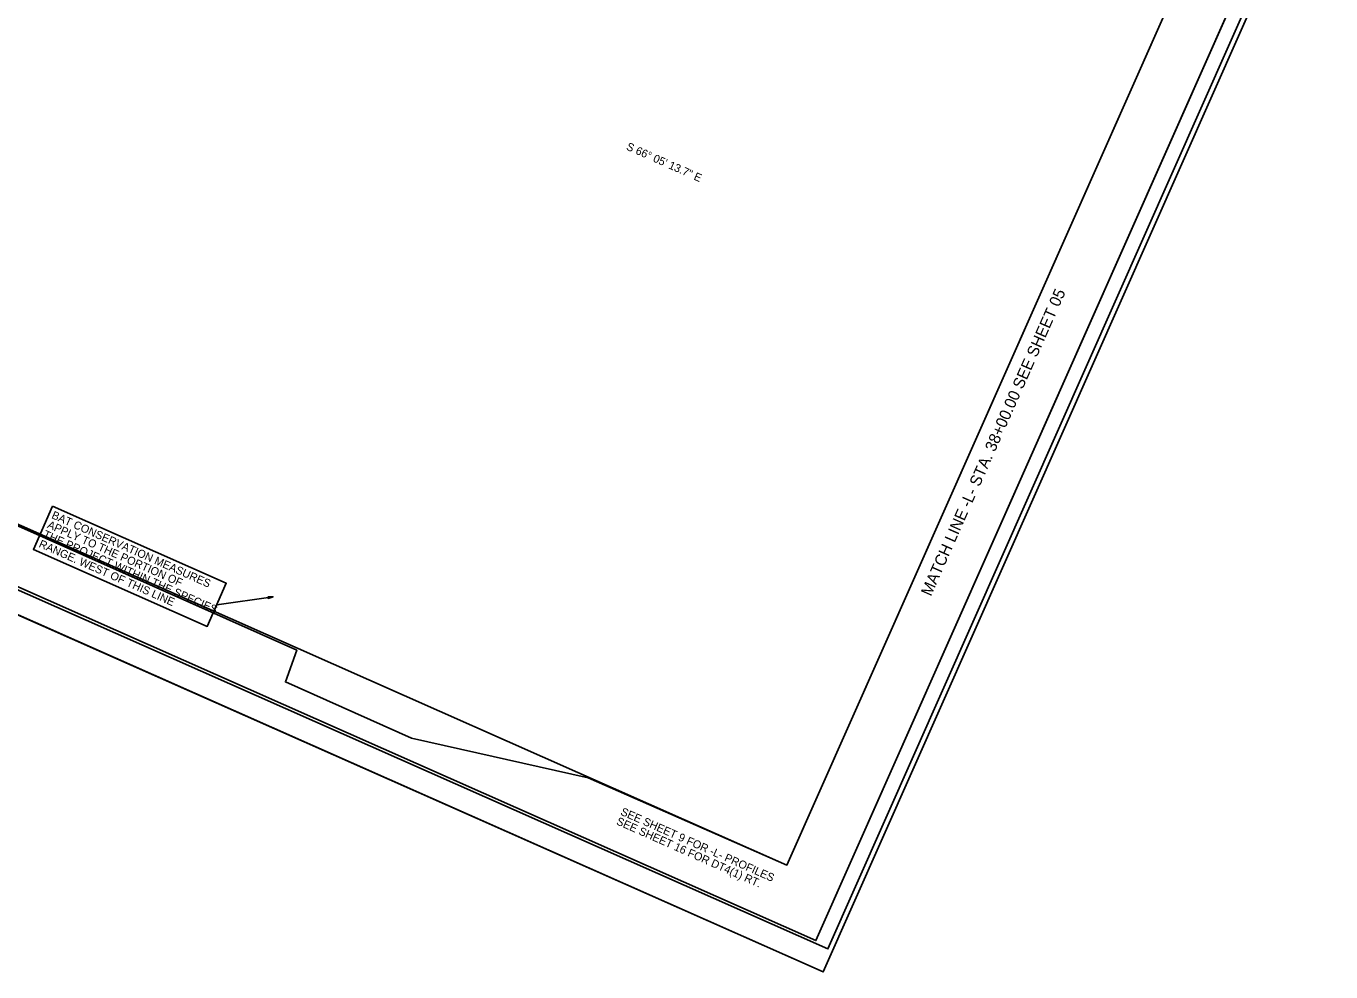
# Model space of a CAD drawing. Extents: x 1637682 to 2864602, y 842496 to 973236.
# Drawn here: x 1638524 to 1639665, y 842496 to 843324 of the extents above; entities that cross this region are included whole.
import ezdxf

# ---------------------------------------------------------------- set-up
doc = ezdxf.new("R2010")
doc.units = 0
for name, color, linetype in [('Matchline', 7, 'Continuous'), ('Matchline Text', 7, 'Continuous'), ('Prop Dimension', 7, 'Continuous'), ('Prop Horizontal Alignment Direction Label', 7, 'Continuous'), ('Sheet Clip Boundary CELL', 7, 'Continuous'), ('Sheet Cutting Line CELL', 7, 'Continuous'), ('Sheet Plan CELL', 7, 'Continuous'), ('Sheet Plot Border Inside CELL', 7, 'Continuous'), ('Sheet Plot Border Outside CELL', 7, 'Continuous')]:
    doc.layers.add(name, color=color, linetype=linetype)

msp = doc.modelspace()

# ---------------------------------------------------------------- linework, layer by layer
at = {"layer": 'Matchline'}
msp.add_line((1639514.6, 843322.7), (1639189.5, 842589.5), dxfattribs=at)
at = {"layer": 'Prop Dimension'}
msp.add_line((1638740.1, 842824.3), (1638690.8, 842817.3), dxfattribs=at)
for points in [[(1638547.2, 842903.5), (1638699.2, 842836.1), (1638682.5, 842798.4), (1638530.5, 842865.8)], [(1638735.5, 842824.4), (1638740.1, 842824.3), (1638735.7, 842822.9), (1638736.1, 842823.7)]]:
    msp.add_lwpolyline(points, close=True, dxfattribs=at)
at = {"layer": 'Sheet Clip Boundary CELL'}
msp.add_lwpolyline([(1638095.3, 843695.6), (1638010.3, 843303.2), (1637949.7, 843324.6), (1637886.3, 843167.4), (1638760.9, 842777.6), (1638750.9, 842749.9), (1638861.2, 842700.7), (1639015.7, 842665.8), (1639189.5, 842589.5), (1639522.8, 843341.2), (1639380.4, 843404.3), (1639446.1, 843552.4), (1639089.1, 843710.7), (1638988.3, 843567.4), (1638956.1, 843552.4), (1638629.8, 843695.5), (1638719.1, 843884.4), (1638267, 844086.3)], close=True, dxfattribs=at)
msp.add_lwpolyline([(1637909.6, 843157), (1639189.5, 842589.5)], dxfattribs=at)
at = {"layer": 'Sheet Cutting Line CELL'}
msp.add_line((1637682.3, 843178.5), (1639221.3, 842496.1), dxfattribs=at)
at = {"layer": 'Sheet Plan CELL'}
for points in [[(1639640.6, 843483.4), (1638269.3, 844091.4), (1637843.7, 843131.6), (1639214.9, 842523.5)], [(1637843.7, 843131.6), (1638269.2, 844091.4), (1639457.7, 843564.5), (1639396.8, 843427.3), (1639579.7, 843346.2), (1639214.9, 842523.5)]]:
    msp.add_lwpolyline(points, close=True, dxfattribs=at)
at = {"layer": 'Sheet Plot Border Inside CELL'}
msp.add_lwpolyline([(1637702.3, 843191.5), (1639225.3, 842516.2), (1639653, 843480.6), (1638130, 844155.9)], close=True, dxfattribs=at)
at = {"layer": 'Sheet Plot Border Outside CELL'}
msp.add_lwpolyline([(1637682.3, 843178.5), (1639221.3, 842496.1), (1639665.2, 843497.1), (1638126.2, 844179.5)], close=True, dxfattribs=at)
msp.add_lwpolyline([(1637682.3, 843178.5), (1639221.3, 842496.1), (1639665.2, 843497.1), (1638126.2, 844179.5)], close=True, dxfattribs=at)

# ---------------------------------------------------------------- texts
at = {"layer": 'Matchline Text'}
msp.add_text('MATCH LINE -L- STA. 38+00.00 SEE SHEET 05', height=10, rotation=66.1362, dxfattribs=at).set_placement((1639315.4, 842824.2))
at = {"layer": 'Prop Dimension'}
for s, p in [('BAT CONSERVATION MEASURES', (1638545.8, 842893.3)), ('THE PROJECT WITHIN THE SPECIES', (1638538.4, 842876.5)), ('APPLY TO THE PORTION OF', (1638542.1, 842884.9)), ('RANGE. WEST OF THIS LINE', (1638534.7, 842868.1)), ('SEE SHEET 9 FOR -L- PROFILES', (1639043.4, 842633.8)), ('SEE SHEET 16 FOR DT4(1) RT.', (1639039.7, 842625.4))]:
    msp.add_text(s, height=7, rotation=336.0871, dxfattribs=at).set_placement(p)
at = {"layer": 'Prop Horizontal Alignment Direction Label'}
msp.add_text('S 66%%d 05\' 13.7" E', height=7, rotation=336.0871, dxfattribs=at).set_placement((1639048.4, 843215.8))

doc.saveas('drawing.dxf')
